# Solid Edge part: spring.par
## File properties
Author: hhakima
Template: Normal.par
Last saved by: hhakima
Revision: 12
Application: Solid Edge
Material: Stainless Steel, 303
Face Style: Steel
Fill Style: ANSI32(Steel)
Virtual Style: Stainless steel
Coef. of Thermal Exp: 1.7e-05
Thermal Conductivity: 17.0
Specific Heat: 502.0
Modulus of Elasticity: 193053196000.0
Poission's Ratio: 0.29
Yield Stress: 255106009.0
Ultimate Stress: 579159588.0
Elongation: 0.0
Density: 8027.000 kg/m^3
Accuracy: 0.990
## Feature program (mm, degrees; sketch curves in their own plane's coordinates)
body "unnamed Body 1"
sketch for "ExtrudedCutout_4" plane through (0.1206, 12.7, 0.7317) normal (0, 1, 0) x-axis (1, 0, 0)
extrude "ExtrudedCutout_4" cut finite 4 along -normal
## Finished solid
Body 1: solid body, 7 faces, 11 edges, 6 vertices.
  Faces by surface: spline 4, plane 3
  Edges by curve: spline 6, intersection 3, circle 1, line 1
Bounding box of the edges (mm; curved faces can reach further): 3.048 x 8.700 x 3.048, from (-1.524, 0, -1.524) to (1.524, 8.7, 1.524).
Planar faces by outward normal: +y 1, +z 1, -y 1
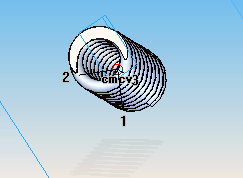
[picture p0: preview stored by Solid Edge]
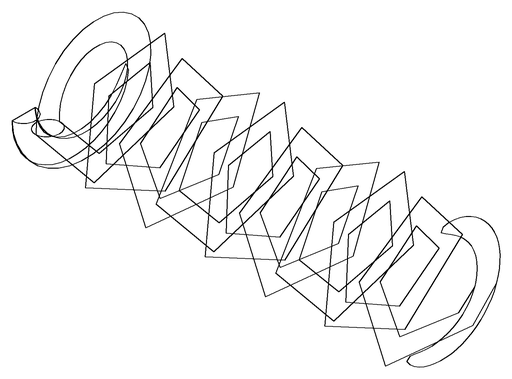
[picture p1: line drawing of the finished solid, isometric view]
